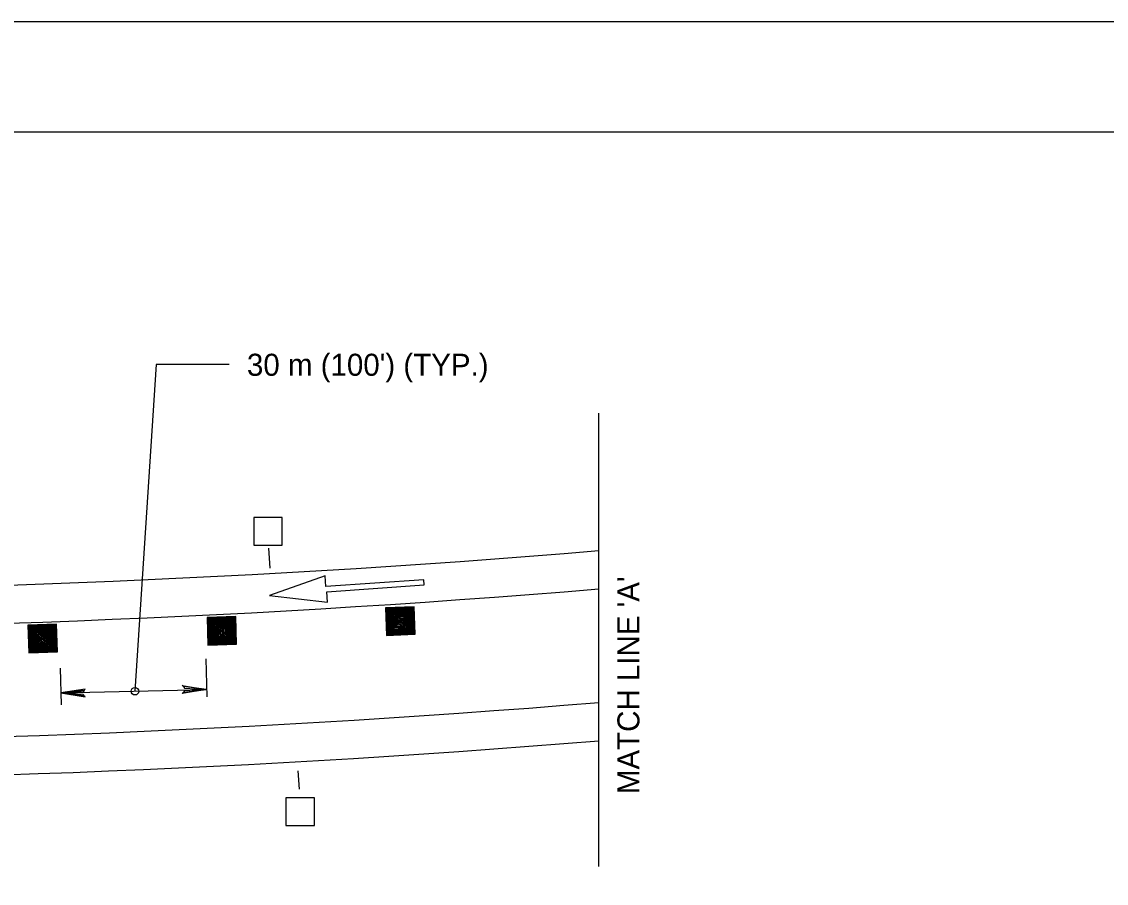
# Model space of a CAD drawing. Extents: x 640253 to 641999, y 298458 to 299646.
# Drawn here: x 641380.3 to 641527.8, y 299528.4 to 299645.6 of the extents above; entities that cross this region are included whole.
import ezdxf

# ---------------------------------------------------------------- set-up
doc = ezdxf.new("R2010")
doc.units = 0
for name, color, linetype in [('1', 7, 'Continuous'), ('2', 7, 'Continuous'), ('PLT-BNDY', 7, 'Continuous')]:
    doc.layers.add(name, color=color, linetype=linetype)

msp = doc.modelspace()

# ---------------------------------------------------------------- linework, layer by layer
at = {"layer": '1'}
msp.add_line((641134.31, 299630.63), (641920.31, 299630.63), dxfattribs=at)
at = {"layer": '2'}
for p, q in [((641458.78, 299530.67), (641458.78, 299592.35)), ((641414.07, 299571.28), (641413.91, 299574.01)), ((641421.56, 299570.22), (641414, 299567.58)), ((641421.66, 299568.78), (641421.56, 299570.22)), ((641434.95, 299569.7), (641421.66, 299568.78)), ((641421.79, 299568.08), (641435, 299568.99)), ((641435, 299568.99), (641434.95, 299569.7)), ((641414, 299567.58), (641421.88, 299566.64)), ((641421.88, 299566.64), (641421.79, 299568.08)), ((641405.33, 299558.94), (641405.46, 299553.77)), ((641385.52, 299557.67), (641385.64, 299552.69)), ((641385.6, 299554.3), (641405.43, 299554.77)), ((641418.05, 299541.21), (641417.9, 299543.69))]:
    msp.add_line(p, q, dxfattribs=at)
for points in [[(641408.49, 299598.98), (641398.57, 299598.98), (641395.68, 299554.54)], [(641429.91, 299562.14), (641433.81, 299562.28), (641433.68, 299566.02), (641429.78, 299565.88), (641429.91, 299562.14), (641433.62, 299565.95), (641429.85, 299565.82), (641429.98, 299562.19), (641433.74, 299562.32), (641433.62, 299565.88), (641429.93, 299565.75), (641430.05, 299562.26), (641433.66, 299562.39), (641433.53, 299565.79), (641430, 299565.66), (641430.12, 299562.32), (641433.59, 299562.45), (641433.48, 299565.73), (641430.07, 299565.61), (641430.18, 299562.39), (641433.51, 299562.51), (641433.39, 299565.66), (641430.14, 299565.54), (641430.24, 299562.45), (641433.44, 299562.58), (641433.32, 299565.58), (641430.21, 299565.47), (641430.31, 299562.52), (641433.37, 299562.64), (641433.25, 299565.51), (641430.28, 299565.4), (641430.36, 299562.6), (641433.28, 299562.72), (641433.19, 299565.42), (641430.37, 299565.33), (641430.43, 299562.65), (641433.18, 299562.79), (641433.1, 299565.35), (641430.45, 299565.26), (641430.5, 299562.72), (641433.1, 299562.85), (641433.02, 299565.29), (641430.53, 299565.19), (641430.58, 299562.76), (641433.01, 299562.91), (641432.92, 299565.21), (641430.63, 299565.1), (641430.61, 299564), (641430.65, 299562.83), (641432.93, 299562.99), (641432.83, 299565.11), (641430.71, 299565), (641430.74, 299562.91), (641432.84, 299563.05), (641432.74, 299565.03), (641430.82, 299564.9), (641430.84, 299563), (641432.71, 299563.12), (641432.63, 299564.9), (641430.96, 299564.8), (641430.96, 299563.14), (641432.56, 299563.22), (641432.49, 299564.79), (641431.12, 299564.68), (641431.09, 299563.26), (641431.1, 299563.26), (641432.41, 299563.35), (641432.36, 299564.64), (641431.26, 299564.56), (641431.23, 299563.39), (641432.25, 299563.49), (641432.22, 299564.48), (641431.4, 299564.43), (641431.39, 299563.55), (641432.09, 299563.6), (641432.04, 299564.34), (641431.57, 299564.3), (641431.57, 299563.69), (641431.91, 299563.74), (641431.9, 299564.18), (641431.75, 299564.21), (641431.74, 299563.85)], [(641405.61, 299560.8), (641409.51, 299560.94), (641409.38, 299564.69), (641405.48, 299564.55), (641405.61, 299560.8), (641409.32, 299564.61), (641405.55, 299564.48), (641405.68, 299560.86), (641409.45, 299560.99), (641409.32, 299564.55), (641405.63, 299564.42), (641405.75, 299560.93), (641409.36, 299561.05), (641409.24, 299564.45), (641405.7, 299564.33), (641405.82, 299560.99), (641409.29, 299561.11), (641409.18, 299564.39), (641405.77, 299564.27), (641405.88, 299561.05), (641409.22, 299561.17), (641409.09, 299564.32), (641405.84, 299564.21), (641405.94, 299561.11), (641409.14, 299561.24), (641409.02, 299564.25), (641405.91, 299564.14), (641406.01, 299561.18), (641409.07, 299561.31), (641408.96, 299564.17), (641405.98, 299564.07), (641406.06, 299561.26), (641408.98, 299561.38), (641408.89, 299564.08), (641406.07, 299563.99), (641406.13, 299561.31), (641408.88, 299561.46), (641408.8, 299564.02), (641406.15, 299563.93), (641406.2, 299561.38), (641408.8, 299561.51), (641408.72, 299563.96), (641406.23, 299563.85), (641406.28, 299561.42), (641408.71, 299561.58), (641408.62, 299563.88), (641406.33, 299563.77), (641406.31, 299562.67), (641406.36, 299561.5), (641408.63, 299561.65), (641408.53, 299563.78), (641406.41, 299563.66), (641406.44, 299561.58), (641408.54, 299561.72), (641408.44, 299563.7), (641406.51, 299563.57), (641406.55, 299561.67), (641408.41, 299561.78), (641408.33, 299563.56), (641406.66, 299563.47), (641406.66, 299561.8), (641408.26, 299561.88), (641408.19, 299563.45), (641406.82, 299563.35), (641406.79, 299561.92), (641406.8, 299561.92), (641408.11, 299562.02), (641408.06, 299563.3), (641406.96, 299563.22), (641406.93, 299562.05), (641407.95, 299562.15), (641407.93, 299563.14), (641407.1, 299563.09), (641407.09, 299562.21), (641407.79, 299562.27), (641407.74, 299563.01), (641407.27, 299562.96), (641407.27, 299562.36), (641407.61, 299562.4), (641407.59, 299562.85), (641407.45, 299562.87), (641407.44, 299562.51)], [(641381.24, 299559.77), (641385.14, 299559.9), (641385.01, 299563.65), (641381.11, 299563.51), (641381.24, 299559.77), (641384.95, 299563.57), (641381.18, 299563.44), (641381.3, 299559.82), (641385.07, 299559.95), (641384.95, 299563.51), (641381.26, 299563.38), (641381.38, 299559.89), (641384.99, 299560.02), (641384.86, 299563.42), (641381.33, 299563.29), (641381.45, 299559.95), (641384.92, 299560.07), (641384.81, 299563.36), (641381.4, 299563.24), (641381.51, 299560.01), (641384.84, 299560.14), (641384.72, 299563.28), (641381.47, 299563.17), (641381.57, 299560.07), (641384.77, 299560.2), (641384.65, 299563.21), (641381.54, 299563.1), (641381.63, 299560.14), (641384.7, 299560.27), (641384.58, 299563.14), (641381.61, 299563.03), (641381.69, 299560.22), (641384.61, 299560.35), (641384.52, 299563.04), (641381.7, 299562.96), (641381.76, 299560.27), (641384.51, 299560.42), (641384.43, 299562.98), (641381.78, 299562.89), (641381.83, 299560.34), (641384.43, 299560.48), (641384.34, 299562.92), (641381.86, 299562.81), (641381.91, 299560.39), (641384.34, 299560.54), (641384.25, 299562.84), (641381.96, 299562.73), (641381.94, 299561.63), (641381.98, 299560.46), (641384.26, 299560.61), (641384.16, 299562.74), (641382.03, 299562.62), (641382.07, 299560.54), (641384.17, 299560.68), (641384.07, 299562.66), (641382.15, 299562.53), (641382.17, 299560.63), (641384.04, 299560.74), (641383.96, 299562.52), (641382.28, 299562.43), (641382.28, 299560.76), (641383.89, 299560.85), (641383.82, 299562.41), (641382.45, 299562.31), (641382.42, 299560.88), (641382.43, 299560.88), (641383.74, 299560.98), (641383.68, 299562.26), (641382.58, 299562.19), (641382.56, 299561.01), (641383.58, 299561.11), (641383.55, 299562.1), (641382.73, 299562.06), (641382.72, 299561.17), (641383.42, 299561.23), (641383.36, 299561.97), (641382.9, 299561.92), (641382.9, 299561.32), (641383.24, 299561.36), (641383.23, 299561.81), (641383.08, 299561.83), (641383.07, 299561.47)], [(641388.76, 299554.7), (641388.64, 299554.47), (641385.6, 299554.3), (641388.76, 299554.7), (641388.91, 299554.84), (641385.6, 299554.3), (641388.64, 299554.14), (641388.74, 299553.92), (641385.6, 299554.3), (641388.91, 299553.78), (641388.74, 299553.92)], [(641402.27, 299555.17), (641402.4, 299554.94), (641405.43, 299554.77), (641402.27, 299555.17), (641402.12, 299555.31), (641405.43, 299554.77), (641402.4, 299554.61), (641402.29, 299554.39), (641405.43, 299554.77), (641402.12, 299554.25), (641402.29, 299554.39)]]:
    msp.add_lwpolyline(points, dxfattribs=at)
for points in [[(641411.83, 299574.43), (641415.72, 299574.43), (641415.72, 299578.17), (641411.83, 299578.17)], [(641416.2, 299536.29), (641420.1, 299536.29), (641420.1, 299540.04), (641416.2, 299540.04)]]:
    msp.add_lwpolyline(points, close=True, dxfattribs=at)
msp.add_circle((641395.68, 299554.54), 0.515, dxfattribs=at)
for radius, start, end in [(1613.21, 264.03084, 274.7698), (1618.4, 264.02808, 274.75447), (1633.8, 264.01999, 274.70955), (1638.99, 264.0173, 274.6946)]:
    msp.add_arc((641324.62, 301181.29), radius, start, end, dxfattribs=at)
at = {"layer": 'PLT-BNDY'}
msp.add_lwpolyline([(641094.31, 299645.63), (641935.31, 299645.63), (641935.31, 299051.63), (641094.31, 299051.63)], close=True, dxfattribs=at)

# ---------------------------------------------------------------- texts
at = {"layer": '2'}
msp.add_text("30 m (100') (TYP.)", height=3, dxfattribs=at).set_placement((641410.91, 299597.45))
msp.add_text("MATCH LINE 'A'", height=3, rotation=90, dxfattribs=at).set_placement((641464.3, 299540.54))

doc.saveas('drawing.dxf')
